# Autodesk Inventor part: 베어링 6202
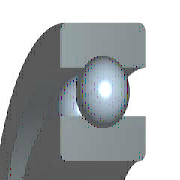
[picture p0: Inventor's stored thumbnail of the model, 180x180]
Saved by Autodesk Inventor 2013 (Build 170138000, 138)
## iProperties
IsCustomPart: 1
Created: 2015-09
Part Number: 베어링 6202
Material: 강, 연강
Description: 깊은 그루브 볼 베어링
Document SubType Name: Modeling
Standard: KS B 2023
Designer: mduedu
Standards Organization: KS
Language: ko-KR
Size Designation: 6202 - 15 x 35 x 11
Categories: <MemberInstance><Categories><Category DisplayName="샤프트 부품" InternalName="7f7aeb1f-a693-4053-b835-cee3144e0d98" Mnemonic="SHFT"><Category DisplayName="베어링" Inter
Density: 7.86 g/cm^3
Mass: 45.8725 g
Surface Area: 51.5584 cm^2
Volume: 5.83619 cm^3
Author: mduedu
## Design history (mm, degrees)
sketch "스케치" dims "d0" = 5.2 (= -0.26 x WD + 0.26 x BD)
  geometry: L1 (2.9, 12.5)-(8.1, 12.5); L2 (5.5, 12.5)-(5.5, 9.9); L3 (5.5, 12.5)-(5.5, 15.1); L4 (3.568, 10.76)-(0, 10.76); L5 (0, 7.5)-(11, 7.5); L6 (3.568, 14.24)-(0, 14.24); L7 (0, 17.5)-(11, 17.5); L8 (11, 7.5)-(11, 10.76); L9 (7.432, 10.76)-(11, 10.76); L10 (7.432, 14.24)-(11, 14.24); L11 (11, 17.5)-(11, 14.24); L12 (-1.4, 0)-(8.4, 0) reference; L13 (0, -0.3)-(0, 5.3) reference
  constraints: 22 end point, 4 point on line, 2 collinear, 2 perpendicular, 2 symmetric about line, 1 midpoint, 1 parallel, 14 other
  dimensions: "d9" = 15 diameter of L5 L12 (= WD); "d11" = 35 diameter of L7 L12 (= BD); "d12" = 11 distance between parallel lines of L8 L13 (= KB); "d13" = 21.52 diameter of L9 L12 (= 0.326 x BD + 0.674 x WD)
revolve "본체" stored, may be unused: angle "d6" = 90 deg
revolve "볼" stored, may be unused: angle "d7" = 90 deg
pattern_circular "IDS_ARRAYBALL[SIMPL:T]" dims angle "d3" = 360 deg
body "Solid1"
fillet "모깎기1" dims "d1" = 0.6 (= KRS)
other parameters: "WD" = 15 [user parameter; used in 5 equation terms], "BD" = 35 [user parameter; used in 5 equation terms], "KB" = 11 [user parameter; used in 1 equation term], "KRS" = 0.6 [user parameter; used in 1 equation term], "d4" = 0, "d5" = 0, "d8" = 0, "d14" = 0, "d15" = 0, "BBA" = 0 [user parameter], "BC0" = 3750000 [user parameter], "BC" = 7800000 [user parameter], "BR" = 17.5 (= 0.5 x BD) [user parameter], "WR" = 7.5 (= 0.5 x WD) [user parameter]
